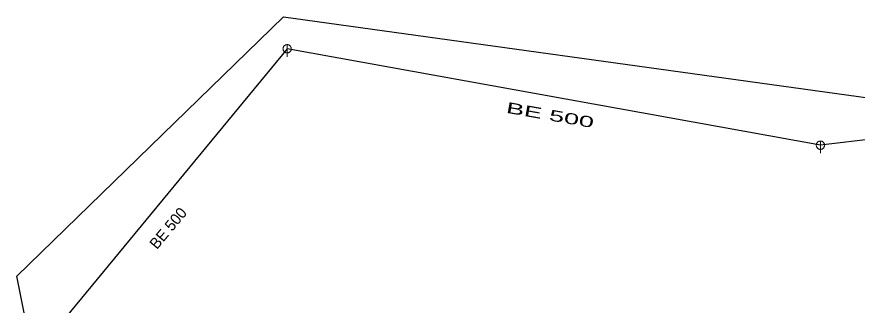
# Model space of a CAD drawing. Extents: x -687515 to -686506, y -974029 to -973461.
# Drawn here: x -687165.8 to -687114.5, y -973894.7 to -973877.2 of the extents above; entities that cross this region are included whole.
import ezdxf
from ezdxf.enums import TextEntityAlignment as Align

# ---------------------------------------------------------------- set-up
doc = ezdxf.new("R2010")
doc.units = 0
doc.header["$LTSCALE"] = 0.27
for name, color, linetype, lineweight in [('1', 7, 'Continuous', 13), ('14', 7, 'Continuous', 25), ('17', 7, 'Continuous', 25), ('22', 7, 'Continuous', 13)]:
    doc.layers.add(name, color=color, linetype=linetype, lineweight=lineweight)

msp = doc.modelspace()

# ---------------------------------------------------------------- linework, layer by layer
at = {"layer": '14'}
for p, q in [((-687149.333, -973879.12), (-687164.024, -973896.907)), ((-687116.789, -973885), (-687149.333, -973879.12)), ((-687098.575, -973882.82), (-687116.789, -973885))]:
    msp.add_line(p, q, dxfattribs=at)
at = {"layer": '17'}
msp.add_lwpolyline([(-687124.395, -974028.598), (-687113.714, -974021.973), (-687139.989, -973975.271), (-687160.068, -973921.704), (-687165.829, -973892.978), (-687149.548, -973877.175), (-687105.661, -973883.258)], dxfattribs=at)
at = {"layer": '22'}
for p, q in [((-687149.332, -973878.868), (-687149.333, -973879.612)), ((-687116.788, -973884.748), (-687116.789, -973885.492))]:
    msp.add_line(p, q, dxfattribs=at)
for points in [[(-687149.081, -973879.12), (-687149.082, -973879.094), (-687149.086, -973879.068), (-687149.092, -973879.042), (-687149.102, -973879.018), (-687149.114, -973878.994), (-687149.128, -973878.972), (-687149.145, -973878.951), (-687149.163, -973878.933), (-687149.184, -973878.916), (-687149.206, -973878.902), (-687149.23, -973878.89), (-687149.254, -973878.88), (-687149.28, -973878.874), (-687149.306, -973878.87), (-687149.332, -973878.868), (-687149.358, -973878.869), (-687149.384, -973878.873), (-687149.41, -973878.879), (-687149.435, -973878.889), (-687149.458, -973878.901), (-687149.48, -973878.915), (-687149.501, -973878.932), (-687149.519, -973878.95), (-687149.536, -973878.971), (-687149.55, -973878.993), (-687149.562, -973879.017), (-687149.572, -973879.041), (-687149.579, -973879.067), (-687149.583, -973879.093), (-687149.585, -973879.119), (-687149.584, -973879.145), (-687149.58, -973879.171), (-687149.573, -973879.197), (-687149.563, -973879.222), (-687149.551, -973879.245), (-687149.537, -973879.267), (-687149.52, -973879.288), (-687149.502, -973879.306), (-687149.481, -973879.323), (-687149.459, -973879.337), (-687149.436, -973879.349), (-687149.411, -973879.359), (-687149.385, -973879.366), (-687149.359, -973879.37), (-687149.333, -973879.372), (-687149.307, -973879.371), (-687149.281, -973879.367), (-687149.255, -973879.36), (-687149.231, -973879.35), (-687149.207, -973879.338), (-687149.185, -973879.324), (-687149.164, -973879.307), (-687149.146, -973879.289), (-687149.129, -973879.268), (-687149.115, -973879.246), (-687149.103, -973879.223), (-687149.093, -973879.198), (-687149.087, -973879.172), (-687149.083, -973879.146)], [(-687116.537, -973885), (-687116.538, -973884.974), (-687116.542, -973884.948), (-687116.548, -973884.922), (-687116.558, -973884.898), (-687116.57, -973884.874), (-687116.584, -973884.852), (-687116.601, -973884.831), (-687116.619, -973884.813), (-687116.64, -973884.796), (-687116.662, -973884.782), (-687116.686, -973884.77), (-687116.71, -973884.76), (-687116.736, -973884.754), (-687116.762, -973884.75), (-687116.788, -973884.748), (-687116.814, -973884.749), (-687116.84, -973884.753), (-687116.866, -973884.759), (-687116.891, -973884.769), (-687116.914, -973884.781), (-687116.936, -973884.795), (-687116.957, -973884.812), (-687116.975, -973884.83), (-687116.992, -973884.851), (-687117.006, -973884.873), (-687117.018, -973884.897), (-687117.028, -973884.921), (-687117.035, -973884.947), (-687117.039, -973884.973), (-687117.041, -973884.999), (-687117.04, -973885.025), (-687117.036, -973885.051), (-687117.029, -973885.077), (-687117.019, -973885.102), (-687117.007, -973885.125), (-687116.993, -973885.147), (-687116.976, -973885.168), (-687116.958, -973885.186), (-687116.937, -973885.203), (-687116.915, -973885.217), (-687116.892, -973885.229), (-687116.867, -973885.239), (-687116.841, -973885.246), (-687116.815, -973885.25), (-687116.789, -973885.252), (-687116.763, -973885.251), (-687116.737, -973885.247), (-687116.711, -973885.24), (-687116.687, -973885.23), (-687116.663, -973885.218), (-687116.641, -973885.204), (-687116.62, -973885.187), (-687116.602, -973885.169), (-687116.585, -973885.148), (-687116.571, -973885.126), (-687116.559, -973885.103), (-687116.549, -973885.078), (-687116.543, -973885.052), (-687116.539, -973885.026)]]:
    msp.add_lwpolyline(points, close=True, dxfattribs=at)

# ---------------------------------------------------------------- texts
at = {"layer": '1', "width": 1.85}
msp.add_text('BE 500', height=0.6667, rotation=350, dxfattribs=at).set_placement((-687133.339, -973883.485), align=Align.CENTER)
at = {"layer": '1'}
msp.add_text('BE 500', height=0.6667, rotation=50, dxfattribs=at).set_placement((-687156.339, -973890.267), align=Align.CENTER)

doc.saveas('drawing.dxf')
